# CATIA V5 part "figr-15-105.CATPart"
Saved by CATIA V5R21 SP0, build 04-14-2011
Part number: Part1
Bounding box of the stored display mesh (mm): x -66.07 to 66.07, y -35.456 to 35.456, z -8 to 1
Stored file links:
  D:\CATIA V5R21 E-RESOURCES\CATIA-V5R21\catia-v5r21-prt\c15-catia-v5r20-prt\c15-catia-v5r21-figr-15-105.CATPart
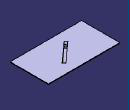
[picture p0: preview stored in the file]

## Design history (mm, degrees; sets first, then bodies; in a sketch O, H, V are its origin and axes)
SheetMetalParameters1: Thickness 1, BendRadius 5, KFactor 0.5 {= log(min(100,max(20*SheetMetalParameters1.BendRadius,SheetMetalParameters1.Thickness)/SheetMetalParameters1.Thickness))/log(100)/2}, ReliefRadialLength 1, ReliefAxialLength 2, MinimumBendRadius 0
Body1 (main body)
  Sketch1 on xy-plane, origin (0, 0, 0), H (1, 0, 0), V (0, 1, 0)
    line L1 (66.07, 35.4565) -> (66.07, -35.4565)
    line L2 (66.07, -35.4565) -> (-66.07, -35.4565)
    line L3 (-66.07, -35.4565) -> (-66.07, 35.4565)
    line L4 (-66.07, 35.4565) -> (66.07, 35.4565)
    vertical: L1 V, L3 V
    horizontal: L2 H, L4 H
    equidistance: L1 L3 O, L2 L4 O
  Wall1: Thickness 1, Profile Sketch1
  Sketch2 on face of Wall1, origin (0, 0, 1), H (1, 0, 0), V (0, 1, 0)
    point P1 (0, 0)
    coincidence: P1 O
  Sketch3 on face of Wall1, origin (0, 0, 1), H (1, 0, 0), V (0, 1, 0)
    point P1 (0, 0)
    reference projected point E1 (0, 0) from Sketch2.P1
    coincidence: E1 P1
  d_Stamp1: Stamp_FilletRadius 2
